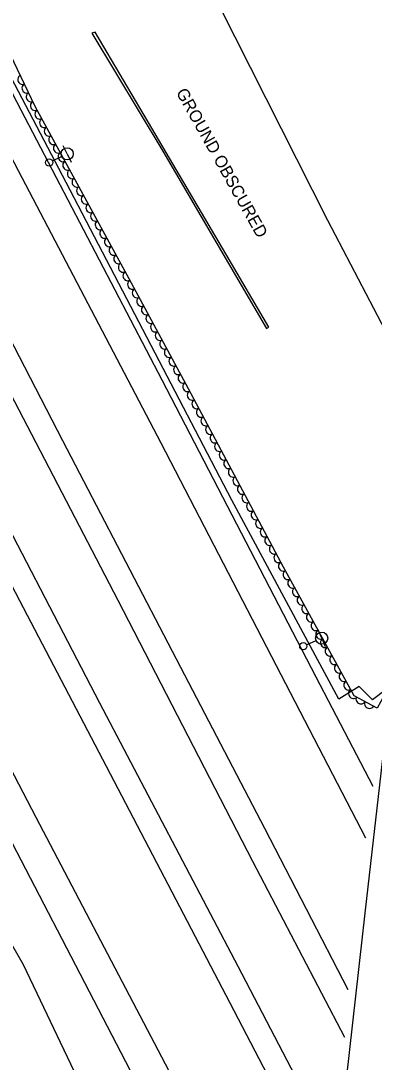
# Model space of a CAD drawing. Extents: x 1722896 to 1754269, y 648279 to 666297.
# Drawn here: x 1727288.7 to 1727434.5, y 654939.2 to 655369.2 of the extents above; entities that cross this region are included whole.
import ezdxf

# ---------------------------------------------------------------- set-up
doc = ezdxf.new("R2010")
doc.units = 0
for name, color, linetype in [('DESIGN - CENTERLINE - Proposed', 7, 'Continuous'), ('DESIGN - SCRATCH - User 1', 7, 'Continuous'), ('SURVEY - CENTERLINE - Preliminary', 7, 'Continuous'), ('SURVEY - CENTERLINE - Preliminary Text', 7, 'Continuous'), ('SURVEY - DTM - Breaklines', 7, 'Continuous'), ('SURVEY - VEGETATION - Features with Text', 7, 'Continuous')]:
    doc.layers.add(name, color=color, linetype=linetype)

msp = doc.modelspace()

# ---------------------------------------------------------------- linework, layer by layer
at = {"layer": 'DESIGN - CENTERLINE - Proposed'}
msp.add_lwpolyline([(1727445.16, 655125.13), (1727466.52, 655085.1), (1727487.76, 655043.93), (1727480.43, 654978.74), (1727473.31, 654916.33), (1727464.6, 654840.82), (1727455.4, 654759.01), (1727440.95, 654630.28), (1727419.27, 654673.34), (1727398.1, 654713.7), (1727404.97, 654771.11), (1727417.79, 654885.73), (1727430.88, 655001.95), (1727444.96, 655124.76)], dxfattribs=at)
at = {"layer": 'DESIGN - SCRATCH - User 1'}
msp.add_lwpolyline([(1727318, 655364.2), (1727347.2, 655315.37), (1727390.01, 655242.2), (1727390.95, 655242.73), (1727373.29, 655273), (1727342.67, 655324.85), (1727319.27, 655364.54), (1727318, 655364.2)], dxfattribs=at)
at = {"layer": 'SURVEY - CENTERLINE - Preliminary'}
for points in [[(1727050.93, 655997.46), (1727319.54, 655476.24), (1727415.27, 655286.88), (1727453.23, 655214.2), (1727438.11, 655205.48), (1727457.2, 655189.9), (1727448.48, 655166.48), (1727444.02, 655127.24), (1727439.46, 655093.12), (1727433.8, 655088.89), (1727428.25, 655094.4), (1727419.84, 655089.11), (1727375.69, 655171.33), (1727307.43, 655302.49), (1727245.01, 655421.37), (1727156.13, 655593.14), (1727078.69, 655739.86)], [(1726991.54, 655469.41), (1727009.94, 655429.47), (1727026.88, 655432.04), (1727047.15, 655427.08), (1727056.25, 655411.45), (1727045.74, 655397.08), (1727056.29, 655384.49), (1727071.84, 655354.73), (1727088.73, 655319.71), (1727100.12, 655302.58), (1727113.92, 655301.43), (1727139.01, 655258.06), (1727145.04, 655222.9), (1727160.32, 655194.52), (1727183.49, 655172.84), (1727194.06, 655165.81), (1727196.41, 655147.13), (1727228.96, 655089.62), (1727256.66, 655036.95), (1727289.64, 654979.52), (1727310.57, 654935.67)]]:
    msp.add_lwpolyline(points, dxfattribs=at)
at = {"layer": 'SURVEY - CENTERLINE - Preliminary Text'}
for points in [[(1727430.98, 655031.8), (1727394.15, 655102.88), (1727346.51, 655194.9), (1727287.74, 655307.34), (1727233.01, 655412.26), (1727188.36, 655497.8), (1727137.6, 655594.68), (1727085.89, 655693.78), (1727040.29, 655781.67), (1726997.3, 655864.1), (1726943.89, 655966.68), (1726889.76, 656071.1), (1726869.43, 656110.45)], [(1726846.62, 656077.71), (1726885.95, 656002.15), (1726927.22, 655922.29), (1726983.5, 655814.13), (1727022.39, 655739.26), (1727067.18, 655653.52), (1727111.82, 655568.21), (1727163.64, 655468.68), (1727209.95, 655380.01), (1727234.58, 655332.9), (1727267.68, 655269.53), (1727305.79, 655195.97), (1727354.57, 655102.28), (1727389.25, 655035.86), (1727423.58, 654969.23)], [(1726839.91, 656067.87), (1726882.05, 655986.55), (1726933.73, 655887.03), (1726971.56, 655814.56), (1727006.02, 655748.53), (1727056.33, 655652.57), (1727112.01, 655545.31), (1727165.4, 655443.03), (1727221.85, 655335.71), (1727276.94, 655229.28), (1727328.71, 655129.98), (1727384.25, 655022.22), (1727422.31, 654949.62)], [(1727416.98, 654904.63), (1727378.29, 654978.72), (1727321.29, 655087.5), (1727268.42, 655189.04), (1727213.71, 655294.11), (1727156.81, 655402.66), (1727090.94, 655530.66), (1727012.29, 655680.77), (1726949.66, 655800.15), (1726895.61, 655905.13), (1726842, 656007.31), (1726823.09, 656044.98)], [(1727414.59, 654887.79), (1727375.02, 654963.6), (1727327.13, 655055.34), (1727288.21, 655129.71), (1727244.68, 655213.41), (1727198.49, 655301.86), (1727151.96, 655390.96), (1727111.65, 655468.27), (1727054.78, 655577.19), (1727008.29, 655666.64), (1726955.92, 655767.53), (1726903.37, 655867.77), (1726854.8, 655961.06), (1726816.46, 656035.3)], [(1726940.93, 656000.07), (1726977.52, 655930.16), (1727037.38, 655813.61), (1727080.46, 655731.31), (1727149.57, 655599.48), (1727227.78, 655449.47), (1727288.61, 655332.48), (1727346.8, 655221.05), (1727410.46, 655098.35), (1727433.96, 655053.16)], [(1726781.43, 655985.97), (1726829.45, 655897.57), (1726869.18, 655825.22), (1726909.31, 655751.73), (1726948.09, 655680.26), (1726983.91, 655615.35), (1727016.03, 655555.81), (1727044.76, 655503.92), (1727072.21, 655453.46), (1727115.52, 655374.69), (1727180.59, 655255.85), (1727232.25, 655160.54), (1727294.86, 655040.47), (1727346.73, 654941.45), (1727387.97, 654862.57), (1727407.26, 654824.97)], [(1726773.86, 655976.54), (1726813.76, 655902.53), (1726857.94, 655817.41), (1726910.4, 655720.65), (1726970.72, 655610.86), (1727017.89, 655524.72), (1727074.08, 655422.09), (1727127, 655325.23), (1727167.58, 655250.48), (1727222.79, 655148.67), (1727281.27, 655037.04), (1727354.22, 654896.29), (1727405.34, 654798.17)]]:
    msp.add_lwpolyline(points, dxfattribs=at)
at = {"layer": 'SURVEY - DTM - Breaklines'}
for p, q in [((1727307.75, 655314.3), (1727306.12, 655317.68)), ((1727301.67, 655311.37), (1727305.5, 655313.22)), ((1727307.75, 655314.3), (1727309.38, 655310.92)), ((1727412.82, 655114.3), (1727411.34, 655117.74)), ((1727412.82, 655114.3), (1727414.3, 655110.85)), ((1727406.62, 655111.63), (1727410.53, 655113.31))]:
    msp.add_line(p, q, dxfattribs=at)
for centre, radius in [((1727307.75, 655314.3), 2.5), ((1727300.32, 655310.72), 1.5), ((1727412.82, 655114.3), 2.5), ((1727405.24, 655111.04), 1.5)]:
    msp.add_circle(centre, radius, dxfattribs=at)
at = {"layer": 'SURVEY - VEGETATION - Features with Text'}
msp.add_lwpolyline([(1727453.67, 655212.51), (1727457.83, 655188.29), (1727453.65, 655157.86), (1727448.19, 655124.48), (1727440.3, 655093.72), (1727435.77, 655085.48), (1727426.27, 655090.51), (1727397.05, 655143.65), (1727357.81, 655217.28), (1727333.34, 655262.76), (1727294.62, 655333.84), (1727263.95, 655398.03), (1727239.89, 655436.54), (1727241.53, 655457.79), (1727251.24, 655460.03), (1727261.95, 655458.43), (1727274.41, 655455.03), (1727290.47, 655454.28), (1727307.65, 655457.18), (1727323.13, 655473.7)], dxfattribs=at)
for centre, major_axis in [((1727289.31, 655344.96), (-0.86, 1.8)), ((1727291.03, 655341.35), (-0.86, 1.8)), ((1727292.76, 655337.74), (-0.86, 1.8)), ((1727294.48, 655334.13), (-0.86, 1.8)), ((1727296.38, 655330.61), (-0.96, 1.76)), ((1727298.3, 655327.1), (-0.96, 1.76)), ((1727300.21, 655323.58), (-0.96, 1.76)), ((1727302.12, 655320.07), (-0.96, 1.76)), ((1727304.03, 655316.56), (-0.96, 1.76)), ((1727305.95, 655313.05), (-0.96, 1.76)), ((1727307.86, 655309.53), (-0.96, 1.76)), ((1727309.77, 655306.02), (-0.96, 1.76)), ((1727311.69, 655302.51), (-0.96, 1.76)), ((1727313.6, 655299), (-0.96, 1.76)), ((1727315.51, 655295.48), (-0.96, 1.76)), ((1727317.43, 655291.97), (-0.96, 1.76)), ((1727319.34, 655288.46), (-0.96, 1.76)), ((1727321.25, 655284.94), (-0.96, 1.76)), ((1727323.17, 655281.43), (-0.96, 1.76)), ((1727325.08, 655277.92), (-0.96, 1.76)), ((1727326.99, 655274.41), (-0.96, 1.76)), ((1727328.91, 655270.89), (-0.96, 1.76)), ((1727330.82, 655267.38), (-0.96, 1.76)), ((1727332.73, 655263.87), (-0.96, 1.76)), ((1727334.64, 655260.35), (-0.95, 1.76)), ((1727336.53, 655256.83), (-0.95, 1.76)), ((1727338.43, 655253.3), (-0.95, 1.76)), ((1727340.32, 655249.78), (-0.95, 1.76)), ((1727342.22, 655246.26), (-0.95, 1.76)), ((1727344.11, 655242.74), (-0.95, 1.76)), ((1727346.01, 655239.21), (-0.95, 1.76)), ((1727347.9, 655235.69), (-0.95, 1.76)), ((1727349.8, 655232.17), (-0.95, 1.76)), ((1727351.69, 655228.65), (-0.95, 1.76)), ((1727353.59, 655225.12), (-0.95, 1.76)), ((1727355.49, 655221.6), (-0.95, 1.76)), ((1727357.38, 655218.08), (-0.95, 1.76)), ((1727359.27, 655214.55), (-0.94, 1.76)), ((1727361.15, 655211.02), (-0.94, 1.76)), ((1727363.03, 655207.49), (-0.94, 1.76)), ((1727364.91, 655203.96), (-0.94, 1.76)), ((1727366.79, 655200.43), (-0.94, 1.76)), ((1727368.67, 655196.9), (-0.94, 1.76)), ((1727370.55, 655193.37), (-0.94, 1.76)), ((1727372.43, 655189.84), (-0.94, 1.76)), ((1727374.32, 655186.31), (-0.94, 1.76)), ((1727376.2, 655182.78), (-0.94, 1.76)), ((1727378.08, 655179.25), (-0.94, 1.76)), ((1727379.96, 655175.72), (-0.94, 1.76)), ((1727381.84, 655172.19), (-0.94, 1.76)), ((1727383.72, 655168.66), (-0.94, 1.76)), ((1727385.6, 655165.13), (-0.94, 1.76)), ((1727387.48, 655161.6), (-0.94, 1.76)), ((1727389.37, 655158.07), (-0.94, 1.76)), ((1727391.25, 655154.54), (-0.94, 1.76)), ((1727393.13, 655151.01), (-0.94, 1.76)), ((1727395.01, 655147.48), (-0.94, 1.76)), ((1727396.89, 655143.95), (-0.94, 1.76)), ((1727398.81, 655140.45), (-0.96, 1.75)), ((1727400.74, 655136.94), (-0.96, 1.75)), ((1727402.67, 655133.43), (-0.96, 1.75)), ((1727404.6, 655129.93), (-0.96, 1.75)), ((1727406.52, 655126.42), (-0.96, 1.75)), ((1727408.45, 655122.92), (-0.96, 1.75)), ((1727410.38, 655119.41), (-0.96, 1.75)), ((1727412.3, 655115.91), (-0.96, 1.75)), ((1727414.23, 655112.4), (-0.96, 1.75)), ((1727416.16, 655108.9), (-0.96, 1.75)), ((1727418.09, 655105.39), (-0.96, 1.75)), ((1727420.01, 655101.89), (-0.96, 1.75)), ((1727421.94, 655098.38), (-0.96, 1.75)), ((1727423.87, 655094.88), (-0.96, 1.75)), ((1727425.8, 655091.37), (-0.96, 1.75)), ((1727428.94, 655089.1), (-1.77, 0.94)), ((1727432.47, 655087.23), (-1.77, 0.94))]:
    msp.add_ellipse(centre, major_axis=major_axis, ratio=0.940188, start_param=0, end_param=3.141593, dxfattribs=at)

# ---------------------------------------------------------------- texts
at = {"layer": 'SURVEY - CENTERLINE - Preliminary'}
msp.add_text('GROUND OBSCURED', height=5, rotation=299.2575, dxfattribs=at).set_placement((1727352.56, 655339.69))

doc.saveas('drawing.dxf')
